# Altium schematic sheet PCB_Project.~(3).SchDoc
size 431 x 279 mm; Date: Not shown in title block; ApprovedBy: Not shown in title block; CheckedBy: Not shown in title block; Author: Not shown in title block; CompanyName: Not shown in title block; Engineer: Not shown in title block; Organization: Not shown in title block; Address1: Not shown in title block; Address2: Not shown in title block; Address3: Not shown in title block; Address4: Not shown in title block; DocumentNumber: 1; Revision: Use project parameter SCH_Rev; SheetNumber: 1; SheetTotal: 3; PageSetup: Record=PageOptions¦CenterHorizontal=True¦CenterVertical=True¦PrintScale=1.00¦XCorrection=1.00¦YCorrection=1.00¦PrintKind=0¦BorderSize=5000000¦LeftOffset=0¦BottomOffset=0¦Orientation=2¦PaperLength=1000¦PaperWidth=1000¦Scale=100¦PaperSource=15¦PrintQuality=600¦MediaType=1¦DitherType=10¦PaperKind=Letter¦PrintScaleMode=1
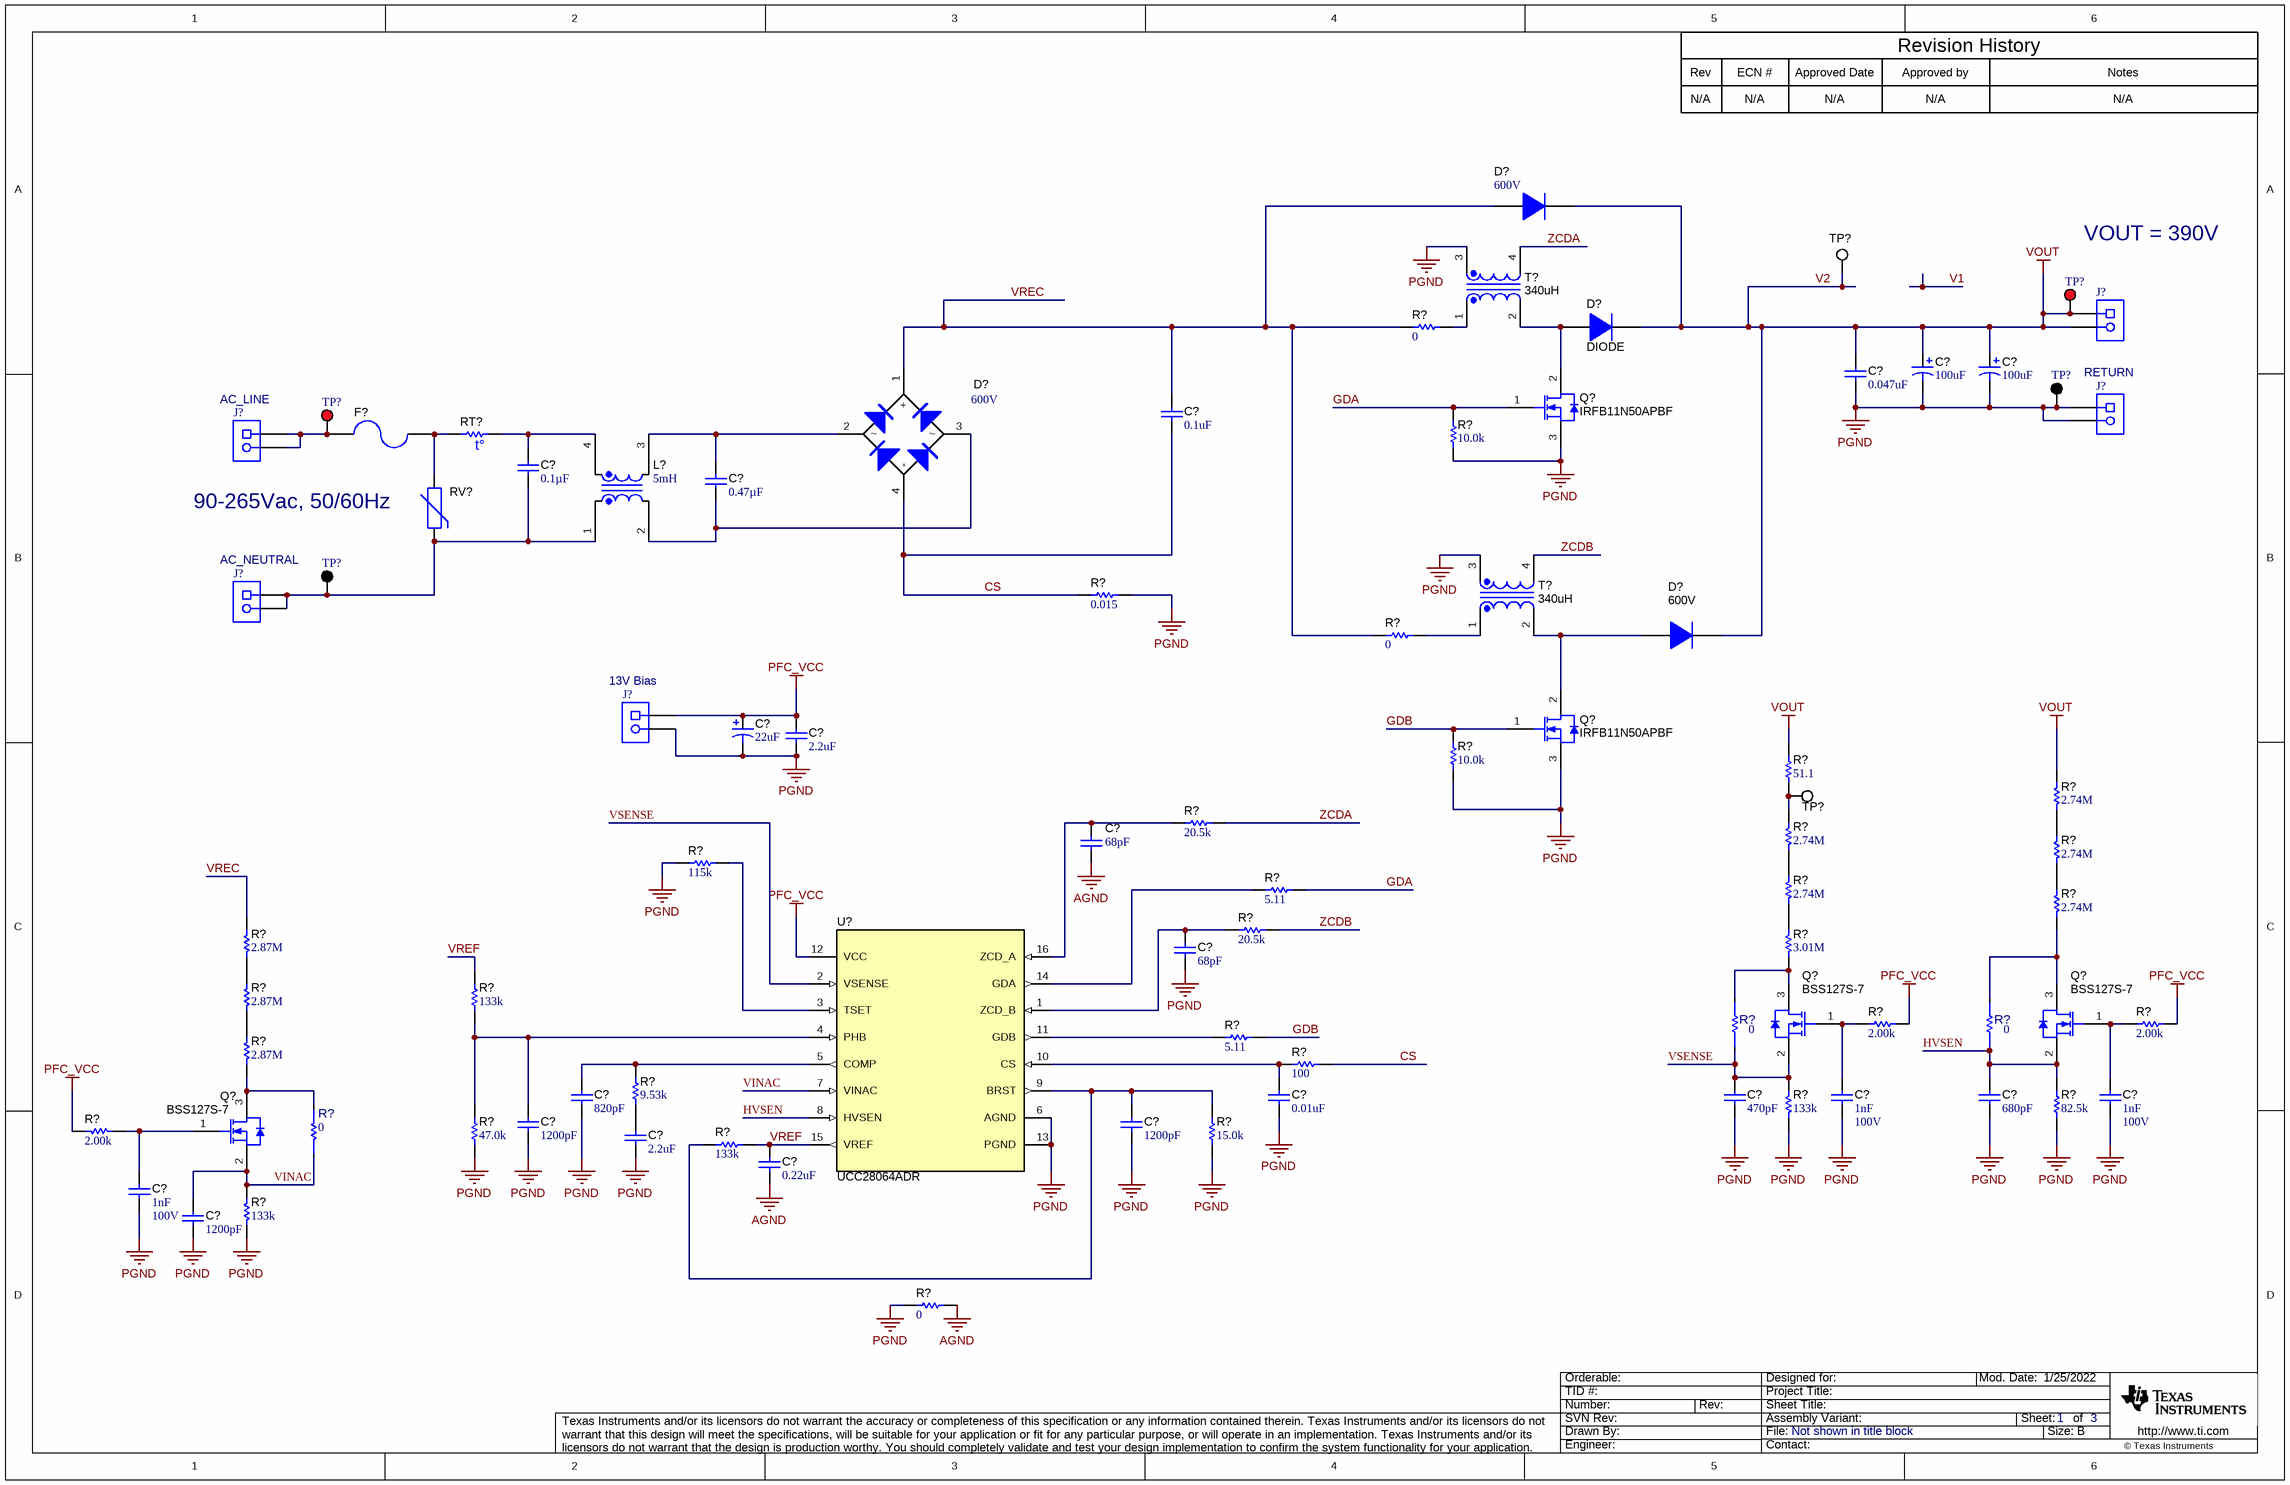
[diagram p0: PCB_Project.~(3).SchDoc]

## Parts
(Parts that share a designator on the sheet are numbered #1, #2 ... from top to bottom, then left to right.)
C?#1  ValueDisplayed: 0.047uF  [ECQE_1200x1450x650]  (hidden comment: Capacitor)
C?#2  ValueDisplayed: 100uF  [KXG_1800x4000_horizontalUp]  (hidden comment: Cap_Polarized)
C?#3  ValueDisplayed: 100uF  [KXG_1800x4000_horizontalDown]  (hidden comment: Cap_Polarized)
C?#4  ValueDisplayed: 0.1uF  [CAPRR1500W60L1750T550H1250]  (hidden comment: Capacitor)
C?#5  ValueDisplayed: 0.1µF  [Kemet_1800x500x1100]  (hidden comment: F863BC104K310Z)
C?#6  ValueDisplayed: 0.47µF  [PHE840M_2600x800x1600]  (hidden comment: PHE840MY6470MD14R06L2)
C?#7  ValueDisplayed: 2.2uF  [0805_HV]  (hidden comment: Capacitor)
C?#8  ValueDisplayed: 22uF  [M_500x1100]  (hidden comment: Cap_Polarized)
C?#9  ValueDisplayed: 68pF  [0805_HV]  (hidden comment: Capacitor)
C?#10  ValueDisplayed: 68pF  [0805_HV]  (hidden comment: Capacitor)
C?#11  ValueDisplayed: 820pF  [0805_HV]  (hidden comment: Capacitor)
C?#12  ValueDisplayed: 0.01uF  [0805_HV]  (hidden comment: Capacitor)
C?#13  ValueDisplayed: 470pF  [0805_HV]  (hidden comment: Capacitor)
C?#14  Cap_F: 1nF  VDC_V: 100V  [0603]  (hidden comment: C1608X7R2A102K080AA)
C?#15  ValueDisplayed: 680pF  [0805_HV]  (hidden comment: Capacitor)
C?#16  Cap_F: 1nF  VDC_V: 100V  [0603]  (hidden comment: C1608X7R2A102K080AA)
C?#17  ValueDisplayed: 1200pF  [0805_HV]  (hidden comment: Capacitor)
C?#18  ValueDisplayed: 1200pF  [0805_HV]  (hidden comment: Capacitor)
C?#19  ValueDisplayed: 2.2uF  [0805_HV]  (hidden comment: Capacitor)
C?#20  ValueDisplayed: 0.22uF  [1206]  (hidden comment: Capacitor)
C?#21  Cap_F: 1nF  VDC_V: 100V  [0603]  (hidden comment: C1608X7R2A102K080AA)
C?#22  ValueDisplayed: 1200pF  [0805_HV]  (hidden comment: Capacitor)
D?#1  Vr_V: 600V  [SMC]  (hidden comment: DIODE)
D?#2  DIODE  [SMC]
D?#3  Vr_V: 600V  [GBU_Horizontal_Down_Standoff2300]  (hidden comment: GBU6J)
D?#4  600V  [SMC]
F?  0216008.MXEP  [FUSE_0216]  (value not drawn)
J?#1  Receptacle_2x1  [On-Shore_ED120_2DS]  (value not drawn)
J?#2  Receptacle_2x1  [On-Shore_ED120_2DS]  (value not drawn)
J?#3  Receptacle_2x1  [On-Shore_ED120_2DS]  (value not drawn)
J?#4  Receptacle_2x1  [On-Shore_ED120_2DS]  (value not drawn)
J?#5  Receptacle_2x1  [On-Shore_ED120_2DS]  (value not drawn)
L?  ValueDisplayed: 5mH  [8100_8109-8114]  (hidden comment: INDUCTOR_COUPLED_12_43)
Q?#1  IRFB11N50APBF  [TO-220AB_Horizontal_100mil_Standoff2300]
Q?#2  IRFB11N50APBF  [TO-220AB_Horizontal_100mil_Standoff2300]
Q?#3  BSS127S-7  [SOT-23]
Q?#4  BSS127S-7  [SOT-23]
Q?#5  BSS127S-7  [SOT-23]
R?#1  ValueDisplayed: 0  [2512]  (hidden comment: Resistor)
R?#2  ValueDisplayed: 10.0k  [0805_HV]  (hidden comment: Resistor)
R?#3  ValueDisplayed: 0.015  [2010]  (hidden comment: Resistor)
R?#4  ValueDisplayed: 0  [2512]  (hidden comment: Resistor)
R?#5  ValueDisplayed: 10.0k  [0805_HV]  (hidden comment: Resistor)
R?#6  ValueDisplayed: 51.1  [0805_HV]  (hidden comment: Resistor)
R?#7  ValueDisplayed: 2.74M  [0805_HV]  (hidden comment: Resistor)
R?#8  ValueDisplayed: 20.5k  [0805_HV]  (hidden comment: Resistor)
R?#9  ValueDisplayed: 2.74M  [0805_HV]  (hidden comment: Resistor)
R?#10  ValueDisplayed: 2.74M  [0805_HV]  (hidden comment: Resistor)
R?#11  ValueDisplayed: 115k  [0805_HV]  (hidden comment: CRCW0805115KFKEA)
R?#12  ValueDisplayed: 5.11  [0805_HV]  (hidden comment: Resistor)
R?#13  ValueDisplayed: 2.74M  [0805_HV]  (hidden comment: Resistor)
R?#14  ValueDisplayed: 2.74M  [0805_HV]  (hidden comment: Resistor)
R?#15  ValueDisplayed: 20.5k  [0805_HV]  (hidden comment: Resistor)
R?#16  ValueDisplayed: 2.87M  [0805_HV]  (hidden comment: Resistor)
R?#17  ValueDisplayed: 3.01M  [0805_HV]  (hidden comment: Resistor)
R?#18  ValueDisplayed: 2.87M  [0805_HV]  (hidden comment: Resistor)
R?#19  ValueDisplayed: 133k  [0805_HV]  (hidden comment: CRCW0805133KFKEA)
R?#20  ValueDisplayed: 2.00k  [0603]  (hidden comment: RC0603FR-072KL)
R?#21  ValueDisplayed: 2.00k  [0603]  (hidden comment: RC0603FR-072KL)
R?#22  ValueDisplayed: 5.11  [0805_HV]  (hidden comment: Resistor)
R?#23  ValueDisplayed: 2.87M  [0805_HV]  (hidden comment: Resistor)
R?#24  value 0  [FP-RMCF1206ZT0R00_1206-MFG]  (hidden comment: RMCF1206ZT0R00)
R?#25  value 0  [FP-RMCF1206ZT0R00_1206-MFG]  (hidden comment: RMCF1206ZT0R00)
R?#26  ValueDisplayed: 100  [0805_HV]  (hidden comment: Resistor)
R?#27  ValueDisplayed: 9.53k  [0805_HV]  (hidden comment: Resistor)
R?#28  ValueDisplayed: 133k  [0805_HV]  (hidden comment: Resistor)
R?#29  ValueDisplayed: 82.5k  [0805_HV]  (hidden comment: Resistor)
R?#30  ValueDisplayed: 2.00k  [0603]  (hidden comment: RC0603FR-072KL)
R?#31  ValueDisplayed: 47.0k  [0805_HV]  (hidden comment: Resistor)
R?#32  ValueDisplayed: 15.0k  [0805_HV]  (hidden comment: CRCW080515K0FKEA)
R?#33  ValueDisplayed: 133k  [0805_HV]  (hidden comment: CRCW0805133KFKEA)
R?#34  value 0  [FP-RMCF1206ZT0R00_1206-MFG]  (hidden comment: RMCF1206ZT0R00)
R?#35  ValueDisplayed: 133k  [0805_HV]  (hidden comment: CRCW0805133KFKEA)
R?#36  ValueDisplayed: 0  [2512]  (hidden comment: Resistor)
RT?  CL-40  [Thermistor_CL-40]  (value not drawn)
RV?  Varistor_MetalOxide  [VAR_S10K275E2]  (value not drawn)
T?#1  340uH  [EATON_CTX16-17769-R]
T?#2  340uH  [EATON_CTX16-17769-R]
TP?#1  5002  [Keystone5002]  (value not drawn)
TP?#2  5010  [Keystone5010]  (value not drawn)
TP?#3  5011  [Keystone5011]  (value not drawn)
TP?#4  5010  [Keystone5010]  (value not drawn)
TP?#5  5011  [Keystone5011]  (value not drawn)
TP?#6  5002  [Keystone5002]  (value not drawn)
U?  UCC28064ADR  [D0016A_N]

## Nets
AGND: C?#9.2 C?#20.2 R?#36.1
PFC_VCC: C?#7.2 C?#8.1(+) J?#5.1 R?#20.2 R?#21.2 R?#30.2 U?.12(VCC)
PGND: C?#1.2 C?#2.2(-) C?#3.2(-) C?#7.1 C?#8.2(-) C?#10.1 C?#11.1 C?#12.2 C?#13.2 C?#14.2 C?#15.2 C?#16.2 C?#17.2 C?#18.2 C?#19.2 C?#21.2 C?#22.1 J?#2.1 J?#2.2 J?#5.2 Q?#1.3(S) Q?#2.3(S) R?#2.1 R?#3.2 R?#5.1 R?#11.1 R?#28.1 R?#29.1 R?#31.1 R?#32.1 R?#35.1 R?#36.2 T?#1.3 T?#2.3 TP?#3.1 U?.6(AGND) U?.13(PGND)
V2: C?#1.1 C?#2.1(+) C?#3.1(+) D?#1.1(K) D?#2.1(K) D?#4.1(K) J?#1.1 J?#1.2 R?#6.2 R?#7.2 TP?#1.1 TP?#2.1  [also labelled VOUT]
CS: C?#4.2 D?#3.4(-) R?#3.1 R?#26.2
GDA: Q?#1.1(G) R?#2.2 R?#12.2
GDB: Q?#2.1(G) R?#5.2 R?#22.2
HVSEN: C?#15.1 Q?#4.2(S) R?#25.1 R?#29.2 U?.8(HVSEN)
VINAC: C?#22.2 Q?#5.2(S) R?#34.1 R?#35.2 U?.7(VINAC)
VREC: C?#4.1 D?#1.2(A) D?#3.1(+) R?#1.1 R?#4.1 R?#16.1
VREF: C?#20.1 R?#19.2 R?#33.2 U?.15(VREF)
VSENSE: C?#13.1 Q?#3.2(S) R?#24.1 R?#28.2 U?.2(VSENSE)
ZCDA: R?#8.1 T?#1.4
ZCDB: R?#15.2 T?#2.4
NetC?#5_1: C?#5.1 L?.4 RT?.2
NetC?#5_2: C?#5.2 J?#4.1 J?#4.2 L?.1 RV?.2 TP?#5.1
NetC?#6_1: C?#6.1 D?#3.2 L?.3
NetC?#6_2: C?#6.2 D?#3.3 L?.2
NetC?#9_1: C?#9.1 R?#8.2 U?.16(ZCD_A)
NetC?#10_2: C?#10.2 R?#15.1 U?.1(ZCD_B)
NetC?#11_2: C?#11.2 R?#27.2 U?.5(COMP)
NetC?#12_1: C?#12.1 R?#26.1 U?.10(CS)
NetC?#14_1: C?#14.1 Q?#3.1(G) R?#20.1
NetC?#16_1: C?#16.1 Q?#4.1(G) R?#21.1
NetC?#17_1: C?#17.1 R?#19.1 R?#31.2 U?.4(PHB)
NetC?#18_1: C?#18.1 R?#32.2 R?#33.1 U?.9(BRST)
NetC?#19_1: C?#19.1 R?#27.1
NetC?#21_1: C?#21.1 Q?#5.1(G) R?#30.1
NetD?#2_2: D?#2.2(A) Q?#1.2(D) T?#1.2
NetD?#4_2: D?#4.2(A) Q?#2.2(D) T?#2.2
NetF?_1: F?.1 RT?.1 RV?.1
NetF?_2: F?.2 J?#3.1 J?#3.2 TP?#4.1
NetQ?#3_3: Q?#3.3(D) R?#17.2 R?#24.2
NetQ?#4_3: Q?#4.3(D) R?#14.1 R?#25.2
NetQ?#5_3: Q?#5.3(D) R?#23.1 R?#34.2
NetR?#1_2: R?#1.2 T?#1.1
NetR?#4_2: R?#4.2 T?#2.1
NetR?#6_1: R?#6.1 R?#9.1 TP?#6.1
NetR?#7_1: R?#7.1 R?#10.2
NetR?#9_2: R?#9.2 R?#13.1
NetR?#10_1: R?#10.1 R?#14.2
NetR?#11_2: R?#11.2 U?.3(TSET)
NetR?#12_1: R?#12.1 U?.14(GDA)
NetR?#13_2: R?#13.2 R?#17.1
NetR?#16_2: R?#16.2 R?#18.1
NetR?#18_2: R?#18.2 R?#23.2
NetR?#22_1: R?#22.1 U?.11(GDB)

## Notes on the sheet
- Rev
- N/A
- ECN #
- Approved Date
- Approved by
- Revision History
- Notes
- VOUT = 390V
- (near J?#3) AC_LINE
- RETURN
- 90-265Vac, 50/60Hz
- (near J?#4) AC_NEUTRAL
- (near J?#5) 13V Bias

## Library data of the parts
C?#1 = CMP-0012494-3: CAP, Film, 0.047 uF, 630 V, +/- 10%, TH; PartNumber: ECQ-E6473KF; Manufacturer: Panasonic; Polarized: N; Cap_F: 47nF; Value1: Unknown; VDC_V: 630V; TaMin_C: -40°C; TaMax_C: 105°C; Cap_Case: 12x14.5x6.5mm; SizeAreaWB_mm2: 119; SizeArea_mm2: 78; SizeX_mm: 12; SizeY_mm: 6.5; SizeZ_mm: 14.5; AEC Category: Q200
C?#2 C?#3 = CMP-0010042-2: CAP, AL, 100 uF, 450 V, +/- 20%, TH; PartNumber: EKXG451ELL101MM40S; Manufacturer: Chemi-Con; Polarized: Y; CompType: Capacitor; Value: 100uF; U/M: EA; Cap_F: 100µF; Value1: Unknown; VDC_V: 450V; IRMS_A: 8dA; TaMin_C: -25°C; TaMax_C: 105°C; Cap_Case: 18x40mm; SizeAreaWB_mm2: 400; SizeArea_mm2: 324; SizeX_mm: 18; SizeZ_mm: 41.5; AEC Category: Q200; AEC Qualified: N
C?#4 = CMP-0012496-3: CAP, Film, 0.1 uF, 275 V, +/- 20%, TH; PartNumber: ECQ-U2A104ML; Manufacturer: Panasonic; Polarized: N; Value: 0.1uF; Cap_F: 100nF; Value1: Unknown; VDC_V: 275V; TaMin_C: -40°C; TaMax_C: 100°C; Cap_Case: Radial 17.5x5.5x12.5; AEC Category: Q200
C?#5 = CMP-0079307-2: CAP, Film, 0.1 µF, X2 310 VAC, +/- 10%, AEC-Q200 Grade 1, TH; Manufacturer: Kemet; Cap_F: 100nF; SizeAreaWB_mm2: 140; SizeArea_mm2: 90; AEC Qualified: Y; AEC Category: Q200; Value: 0.1uF; TaMax_C: 110°C; SizeZ_mm: 11.1; AEC Grade: 1; Polarized: N; TaMin_C: -40°C; SizeY_mm: 5; CompType: Capacitor; SizeX_mm: 18; Cap_Case: 18x5x11mm; VAC_X: 310
C?#6 = CMP-0079470-1: CAP, Film, 0.47 µF, 760 V,+/- 20%, TH; Manufacturer: Kemet; Cap_F: 470nF; SizeAreaWB_mm2: 280; SizeArea_mm2: 208; AEC Qualified: N; AEC Category: Q200; Value: 0.47uF; TaMax_C: 105°C; SizeZ_mm: 16; TaMin_C: -55°C; VDC_V: 760V; SizeY_mm: 8; CompType: Capacitor; SizeX_mm: 26; Cap_Case: 26x8x16mm
C?#7 C?#19 = CMP-0007877-2: CAP, CERM, 2.2 uF, 50 V, +/- 10%, X7R, 0805; PartNumber: C2012X7R1H225K125AC; Manufacturer: TDK; Polarized: N; Value: 2.2uF; U/M: EA; Cap_F: 2.2µF; ESR_ohm: 3.66m; Value1: 0.00366 ohm; VDC_V: 50V; IRMS_A: 3.41207A; TaMin_C: -55°C; TaMax_C: 125°C; Cap_Case: 0805; SizeArea_mm2: 2.5; SizeAreaWB_mm2: 6.75; SizeX_mm: 2; SizeY_mm: 1.25; SizeZ_mm: 1.45; AEC Category: Q200
C?#8 = CMP-0010326-2: CAP, AL, 22 uF, 35 V, +/- 20%, TH; PartNumber: ECA-1VM220; Manufacturer: Panasonic; Polarized: Y; CompType: Capacitor; Value: 22uF; U/M: EA; Cap_F: 22µF; Value1: Unknown; VDC_V: 35V; IRMS_A: 95mA; TaMin_C: -40°C; TaMax_C: 85°C; Cap_Case: 5x11; SizeAreaWB_mm2: 49; SizeArea_mm2: 25; SizeX_mm: 5; SizeZ_mm: 12; AEC Category: Q200; AEC Qualified: N
C?#9 C?#10 = CMP-0007622-2: CAP, CERM, 68 pF, 50 V, +/- 5%, C0G/NP0, 0805; PartNumber: 08055A680JAT2A; Manufacturer: AVX; Polarized: N; Value: 68pF; U/M: EA; ESR_ohm: 4.5d; Value1: 0.45 ohm; VDC_V: 50V; TaMin_C: -55°C; TaMax_C: 125°C; Cap_Case: 0805; SizeArea_mm2: 2.5; SizeAreaWB_mm2: 6.75; SizeX_mm: 2; SizeY_mm: 1.25; SizeZ_mm: 1.45; AEC Category: Q200
C?#11 = CMP-0008153-2: CAP, CERM, 820 pF, 25 V, +/- 10%, X7R, 0805; PartNumber: GRM216R71E821KA01D; Manufacturer: MuRata; Polarized: N; Value: 820pF; U/M: EA; Value1: Unknown; VDC_V: 25V; TaMin_C: -55°C; TaMax_C: 125°C; Cap_Case: 0805; SizeArea_mm2: 2.5; SizeAreaWB_mm2: 6.75; SizeX_mm: 2; SizeY_mm: 1.25; SizeZ_mm: 1.45; AEC Category: Q200
C?#12 = CMP-0007629-2: CAP, CERM, 0.01 uF, 50 V, +/- 5%, X7R, 0805; PartNumber: 08055C103JAT2A; Manufacturer: AVX; Polarized: N; Value: 0.01uF; U/M: EA; Cap_F: 10nF; ESR_ohm: 0.078; Value1: 0.078 ohm; VDC_V: 50V; TaMin_C: -55°C; TaMax_C: 125°C; Cap_Case: 0805; SizeArea_mm2: 2.5; SizeAreaWB_mm2: 6.75; SizeX_mm: 2; SizeY_mm: 1.25; SizeZ_mm: 1.45; AEC Category: Q200
C?#13 = CMP-0008150-2: CAP, CERM, 470 pF, 25 V, +/- 10%, X7R, 0805; PartNumber: GRM216R71E471KA01D; Manufacturer: MuRata; Polarized: N; Value: 470pF; U/M: EA; Value1: Unknown; VDC_V: 25V; TaMin_C: -55°C; TaMax_C: 125°C; Cap_Case: 0805; SizeArea_mm2: 2.5; SizeAreaWB_mm2: 6.75; SizeX_mm: 2; SizeY_mm: 1.25; SizeZ_mm: 1.45; AEC Category: Q200
C?#14 C?#16 C?#21 = CMP-0007053-4: CAP, CERM, 1000 pF, 100 V, +/- 10%, X7R, 0603; Manufacturer: TDK; TaMin_C: -55°C; Polarized: N; SizeAreaWB_mm2: 4.68; Value1: Unknown; U/M: EA; Value: 1000pF; TaMax_C: 125°C; SizeZ_mm: 1; SizeX_mm: 1.6; SizeY_mm: 0.8; SizeArea_mm2: 1.28; AEC Category: Q200
C?#15 = CMP-0007693-2: CAP, CERM, 680 pF, 25 V, +/- 10%, X7R, 0805; PartNumber: 885012207059; Manufacturer: Wurth Elektronik; Polarized: N; Value: 680pF; U/M: EA; Value1: Unknown; VDC_V: 25V; TaMin_C: -55°C; TaMax_C: 125°C; Cap_Case: 0805; SizeArea_mm2: 2.5; SizeAreaWB_mm2: 6.75; SizeX_mm: 2; SizeY_mm: 1.25; SizeZ_mm: 1.45; AEC Category: Q200
C?#17 C?#18 C?#22 = CMP-0008142-2: CAP, CERM, 1200 pF, 25 V, +/- 10%, X7R, 0805; PartNumber: GRM216R71E122KA01D; Manufacturer: MuRata; Polarized: N; Value: 1200pF; U/M: EA; Cap_F: 1.2nF; Value1: Unknown; VDC_V: 25V; TaMin_C: -55°C; TaMax_C: 125°C; Cap_Case: 0805; SizeArea_mm2: 2.5; SizeAreaWB_mm2: 6.75; SizeX_mm: 2; SizeY_mm: 1.25; SizeZ_mm: 1.45; AEC Category: Q200
C?#20 = CMP-0008995-2: CAP, CERM, 0.22 uF, 50 V, +/- 10%, X7R, 1206; PartNumber: GRM31MR71H224KA01L; Manufacturer: MuRata; Polarized: N; Value: 0.22uF; U/M: EA; Cap_F: 220nF; Value1: Unknown; VDC_V: 50V; TaMin_C: -55°C; TaMax_C: 125°C; SizeArea_mm2: 5.12; SizeAreaWB_mm2: 10.92; SizeX_mm: 3.2; SizeY_mm: 1.6; SizeZ_mm: 1.35; AEC Category: Q200
D?#1 D?#2 = CMP-0076905-1: Diode, Ultrafast, 600 V, 3 A, SMC; PartNumber: MURS360T3G; Manufacturer: ON Semiconductor; U/M: EA; Vf_V: 1.25V; Value: 600V; Value1: 3A; TJmax_C: 175°C; RJC_CperW: 11.0; SizeAreaWB_mm2: 83.2686; SizeArea_mm2: 50.5686; SizeX_mm: 8.13; SizeY_mm: 6.22; SizeZ_mm: 2.6; AEC Category: Q101; Green_Lifecycle: Active; Green_REACh: Passed
D?#3 = CMP-0029269-2: Diode, Switching-Bridge, 600 V, 6 A, TH; Manufacturer: Fairchild Semiconductor; U/M: EA; Vf_V: 1V; Value: 600V; Value1: 6A; TJmax_C: 150°C; RJC_CperW: 3.1; SizeAreaWB_mm2: 130.5915; SizeArea_mm2: 75.6315; SizeX_mm: 22.05; SizeY_mm: 3.43; SizeZ_mm: 21.55; AEC Category: Q101; AEC Qualified: N; Green_Lifecycle: Active; Green_REACh: Passed
D?#4 = CMP-0076905-1: Diode, Ultrafast, 600 V, 3 A, SMC; PartNumber: MURS360T3G; Manufacturer: ON Semiconductor; U/M: EA; Vf_V: 1.25V; Value1: 3A; TJmax_C: 175°C; RJC_CperW: 11.0; SizeAreaWB_mm2: 83.2686; SizeArea_mm2: 50.5686; SizeX_mm: 8.13; SizeY_mm: 6.22; SizeZ_mm: 2.6; AEC Category: Q101; Green_Lifecycle: Active; Green_REACh: Passed
F? = CMP-0079917-1: Fuse, 8 A, 250 VAC, TH; Manufacturer: Littelfuse; VAC_V: 250V; Rtyp_Ohm: 0.0123; MeltingTyp: 64.315; Irating_A: 8A; Interrupt_AC: 1.5kA
J?#1-J?#5 = CMP-0074910-1: Terminal Block, 5.08 mm, 2x1, Brass, TH; PartNumber: ED120/2DS; Manufacturer: On-Shore Technology; Pitch_mm: 5.08; Gender: Female; Shrouded: N; Row_Count: 1; Current_A: 15A; Voltage_V: 300V; Cert_CULUS: Y; Green_Lifecycle: Not Set; Green_REACh: Incomplete; CNHeader: False; CT: True
L? = CMP-0076835-1: Coupled inductor, 5 mH, 8.9 A, 0.022 ohm, TH; PartNumber: 8113-RC; Manufacturer: Bourns; Value: 5mH; DCR_ohm: 0.022; Green_Lifecycle: Not Set; Green_REACh: Incomplete; AEC Category: Q200
Q?#1 Q?#2 = CMP-0001125-3: MOSFET, N-CH, 500 V, 11 A, AEC-Q101, TO-220AB; Alternate Manufacturer: None; Manufacturer: Vishay-Siliconix; SizeZ_mm: 19.4; ChType: N; Value2: 52 nC; VdsMax_V: 500V; SizeX_mm: 10.2; SizeY_mm: 4.5; Vgs_V: 30V; AEC Qualified: Y; Value: 500V; SizeArea_mm2: 45.9; AEC Category: Q101; IdsMax_A: 11A; SizeAreaWB_mm2: 79.3; U/M: EA; QgTyp_nC: 52
Q?#3-Q?#5 = CMP-0001149-3: MOSFET, N-CH, 600 V, 0.05 A, SOT-23; Alternate Manufacturer: None; Manufacturer: Diodes Inc.; SizeZ_mm: 1.1; ChType: N; Value2: 1.08 nC; VdsMax_V: 600V; SizeX_mm: 2.5; SizeY_mm: 3; Vgs_V: 20V; QgTyp_nC: 1.08; Value: 600V; SizeArea_mm2: 7.5; AEC Category: Q101; IdsMax_A: 50mA; SizeAreaWB_mm2: 14; U/M: EA
R?#1 R?#4 R?#36 = CMP-0015864-3: RES, 0, 5%, 1 W, AEC-Q200 Grade 0, 2512; PartNumber: CRCW25120000Z0EG; Manufacturer: Vishay-Dale; Value: 0; Value_Code: 0000; Power_W: 1W; TempCo: ppm/C; SizeArea_mm2: 20.16; SizeX_mm: 6.3; SizeY_mm: 3.2; SizeZ_mm: 0.71; EIA_Code: E24; AEC Category: Q200; AEC Qualified: Y
R?#2 R?#5 = CMP-0020842-3: RES, 10.0 k, 1%, 0.125 W, AEC-Q200 Grade 0, 0805; PartNumber: CRCW080510K0FKEA; Manufacturer: Vishay-Dale; Value: 10.0k; Res_ohm: 10k; Value_Code: 10k0; Power_W: 125mW; Value2: 0.125W; VDC_V: 150V; TempCo: 100 ppm/C; SizeArea_mm2: 2.5; SizeX_mm: 2; SizeY_mm: 1.25; SizeZ_mm: 1.45; EIA_Code: E96; AEC Category: Q200; AEC Qualified: Y; AEC Grade: 0
R?#3 = CMP-0016558-2: RES, 0.015, 1%, 0.5 W, 2010; PartNumber: WSL2010R0150FEA; Manufacturer: Vishay-Dale; Value: 0.015; Value_Code: R015; Power_W: 500mW; Value2: 0.5W; TempCo: 75 ppm/C; SizeArea_mm2: 12.5; SizeX_mm: 5; SizeY_mm: 2.5; SizeZ_mm: 1.66; EIA_Code: E96; U/M: EA; AEC Category: Q200
R?#6 = CMP-0020156-2: RES, 51.1, 0.1%, 0.125 W, 0805; PartNumber: RT0805BRD0751R1L; Manufacturer: Yageo America; Value: 51.1; Value_Code: 51R1; Power_W: 125mW; Value2: 0.125W; VDC_V: 150V; TempCo: 25 ppm/C; SizeArea_mm2: 2.5; SizeX_mm: 2; SizeY_mm: 1.25; SizeZ_mm: 1.45; EIA_Code: E192; U/M: EA; AEC Category: Q200
R?#7 R?#9 R?#10 R?#13 R?#14 = CMP-0021137-3: RES, 2.74 M, 1%, 0.125 W, AEC-Q200 Grade 0, 0805; PartNumber: CRCW08052M74FKEA; Manufacturer: Vishay-Dale; Value: 2.74Meg; Value_Code: 2M74; Power_W: 125mW; Value2: 0.125W; VDC_V: 150V; TempCo: 100 ppm/C; SizeArea_mm2: 2.5; SizeX_mm: 2; SizeY_mm: 1.25; SizeZ_mm: 1.45; EIA_Code: E96; AEC Category: Q200; AEC Qualified: Y; AEC Grade: 0
R?#8 R?#15 = CMP-0021043-3: RES, 20.5 k, 1%, 0.125 W, AEC-Q200 Grade 0, 0805; PartNumber: CRCW080520K5FKEA; Manufacturer: Vishay-Dale; Value: 20.5k; Value_Code: 20k5; Power_W: 125mW; Value2: 0.125W; VDC_V: 150V; TempCo: 100 ppm/C; SizeArea_mm2: 2.5; SizeX_mm: 2; SizeY_mm: 1.25; SizeZ_mm: 1.45; EIA_Code: E96; AEC Category: Q200; AEC Qualified: Y; AEC Grade: 0
R?#11 = CMP-0020855-3: RES, 115 k, 1%, 0.125 W, AEC-Q200 Grade 0, 0805; Manufacturer: Vishay-Dale; Power_W: 125mW; TempCo: 100 ppm/C; Value: 115k; EIA_Code: E96; SizeX_mm: 2; SizeY_mm: 1.25; SizeZ_mm: 1.45; Value2: 0.125W; SizeArea_mm2: 2.5; AEC Qualified: Y; VDC_V: 150V; AEC Category: Q200; AEC Grade: 0
R?#12 R?#22 = CMP-0021358-3: RES, 5.11, 1%, 0.125 W, AEC-Q200 Grade 0, 0805; PartNumber: CRCW08055R11FKEA; Manufacturer: Vishay-Dale; Value: 5.11; Value_Code: 5R11; Power_W: 125mW; Value2: 0.125W; VDC_V: 150V; TempCo: 100 ppm/C; SizeArea_mm2: 2.5; SizeX_mm: 2; SizeY_mm: 1.25; SizeZ_mm: 1.45; EIA_Code: E96; AEC Category: Q200; AEC Qualified: Y; AEC Grade: 0
R?#16 R?#18 R?#23 = CMP-0021139-3: RES, 2.87 M, 1%, 0.125 W, AEC-Q200 Grade 0, 0805; PartNumber: CRCW08052M87FKEA; Manufacturer: Vishay-Dale; Value: 2.87Meg; Value_Code: 2M87; Power_W: 125mW; Value2: 0.125W; VDC_V: 150V; TempCo: 100 ppm/C; SizeArea_mm2: 2.5; SizeX_mm: 2; SizeY_mm: 1.25; SizeZ_mm: 1.45; EIA_Code: E96; AEC Category: Q200; AEC Qualified: Y; AEC Grade: 0
R?#17 = CMP-0021219-4: RES, 3.01 M, 1%, 0.125 W, AEC-Q200 Grade 0, 0805; PartNumber: CRCW08053M01FKEA; Manufacturer: Vishay-Dale; Value: 3.01Meg; Value_Code: 3M01; Power_W: 125mW; Value2: 0.125W; VDC_V: 150V; TempCo: 100 ppm/C; SizeArea_mm2: 2.5; SizeX_mm: 2; SizeY_mm: 1.25; SizeZ_mm: 1.45; EIA_Code: E96; AEC Category: Q200; AEC Qualified: Y; AEC Grade: 0
R?#19 R?#33 R?#35 = CMP-0020881-3: RES, 133 k, 1%, 0.125 W, AEC-Q200 Grade 0, 0805; Manufacturer: Vishay-Dale; Power_W: 125mW; TempCo: 100 ppm/C; Value: 133k; EIA_Code: E96; SizeX_mm: 2; SizeY_mm: 1.25; SizeZ_mm: 1.45; Value2: 0.125W; SizeArea_mm2: 2.5; AEC Qualified: Y; VDC_V: 150V; AEC Category: Q200; AEC Grade: 0
R?#20 R?#21 R?#30 = CMP-0023000-5: RES, 2.00 k, 1%, 0.1 W, 0603; Manufacturer: Yageo; Power_W: 100mW; TempCo: 100 ppm/C; Value_Code: 2k00; Value: 2.00k; EIA_Code: E96; Res_ohm: 2k; SizeX_mm: 1.6; SizeY_mm: 0.8; SizeZ_mm: 1; Value2: 0.1W; SizeArea_mm2: 1.28; AEC Qualified: N; VDC_V: 75V; AEC Category: Q200; SizeAreaWB_mm2: 4.68
R?#24 R?#25 R?#34 = CMP-0093609-1: 0Ω ±0 0.25W 1206 Thick Film Chip Resistor AEC-Q200 compliant; Manufacturer: Stackpole Electronics; AEC Qualified: Yes; VDC_V: 200V; AEC Grade: Grade 0; Power_W: 250mW; SizeZ_mm: 0.7mm
R?#26 = CMP-0020835-3: RES, 100, 1%, 0.125 W, AEC-Q200 Grade 0, 0805; PartNumber: CRCW0805100RFKEA; Manufacturer: Vishay-Dale; Value: 100; Value_Code: 100R; Power_W: 125mW; Value2: 0.125W; VDC_V: 150V; TempCo: 100 ppm/C; SizeArea_mm2: 2.5; SizeX_mm: 2; SizeY_mm: 1.25; SizeZ_mm: 1.45; EIA_Code: E96; AEC Category: Q200; AEC Qualified: Y; AEC Grade: 0
R?#27 = CMP-0021817-2: RES, 9.53 k, 1%, 0.125 W, 0805; PartNumber: ERJ-6ENF9531V; Manufacturer: Panasonic; Value: 9.53k; Value_Code: 9k53; Power_W: 125mW; Value2: 0.125W; TempCo: 100 ppm/C; SizeArea_mm2: 2.5; SizeX_mm: 2; SizeY_mm: 1.25; SizeZ_mm: 1.45; EIA_Code: E96; U/M: EA; AEC Category: Q200
R?#28 = CMP-0020881-3: RES, 133 k, 1%, 0.125 W, AEC-Q200 Grade 0, 0805; PartNumber: CRCW0805133KFKEA; Manufacturer: Vishay-Dale; Value: 133k; Power_W: 125mW; Value2: 0.125W; VDC_V: 150V; TempCo: 100 ppm/C; SizeArea_mm2: 2.5; SizeX_mm: 2; SizeY_mm: 1.25; SizeZ_mm: 1.45; EIA_Code: E96; AEC Category: Q200; AEC Qualified: Y; AEC Grade: 0
R?#29 = CMP-0021455-3: RES, 82.5 k, 1%, 0.125 W, AEC-Q200 Grade 0, 0805; PartNumber: CRCW080582K5FKEA; Manufacturer: Vishay-Dale; Value: 82.5k; Value_Code: 82k5; Power_W: 125mW; Value2: 0.125W; VDC_V: 150V; TempCo: 100 ppm/C; SizeArea_mm2: 2.5; SizeX_mm: 2; SizeY_mm: 1.25; SizeZ_mm: 1.45; EIA_Code: E96; AEC Category: Q200; AEC Qualified: Y; AEC Grade: 0
R?#31 = CMP-0021726-2: RES, 47.0 k, 1%, 0.125 W, 0805; PartNumber: ERJ-6ENF4702V; Manufacturer: Panasonic; Value: 47.0k; Res_ohm: 47k; Value_Code: 47k0; Power_W: 125mW; Value2: 0.125W; VDC_V: 150V; TempCo: 100 ppm/C; SizeArea_mm2: 2.5; SizeX_mm: 2; SizeY_mm: 1.25; SizeZ_mm: 1.45; U/M: EA; AEC Category: Q200
R?#32 = CMP-0020909-3: RES, 15.0 k, 1%, 0.125 W, AEC-Q200 Grade 0, 0805; Manufacturer: Vishay-Dale; Power_W: 125mW; TempCo: 100 ppm/C; Value_Code: 15k0; Value: 15.0k; EIA_Code: E96; Res_ohm: 15k; SizeX_mm: 2; SizeY_mm: 1.25; SizeZ_mm: 1.45; Value2: 0.125W; SizeArea_mm2: 2.5; AEC Qualified: Y; VDC_V: 150V; AEC Category: Q200; AEC Grade: 0
RT? = CMP-0002561-2: Thermistor NTC, 5 ohm, 25%, Disc, 220x770 mil; Manufacturer: GE Sensing; Value: 5; Power_W: 180W; TaMin_C: -50°C; TaMax_C: 175°C; SizeAreaWB_mm2: 163.6404; SizeArea_mm2: 109.3404; SizeX_mm: 19.56; SizeY_mm: 5.59; U/M: EA
RV? = CMP-0002100-2: Varistor 275V RMS 10MM Radial, TH; PartNumber: S10K275E2; Manufacturer: TDK; SizeAreaWB_mm2: 103.6; SizeArea_mm2: 64.8; SizeX_mm: 12; SizeY_mm: 5.4; SizeZ_mm: 14.5
T?#1 T?#2 = CMP-0030075-1: Transformer, 340 uH, TH; PartNumber: CTX16-17769-R; Manufacturer: Eaton; DCR_ohm: 2.4d; Lp: 340; Ind_H: 340µH; Ns1toNp: 8; Rsec1_ohm: 0.035; SizeAreaWB_mm2: 1764; SizeArea_mm2: 1600; SizeX_mm: 40; SizeZ_mm: 19.8
TP?#1 TP?#6 = CMP-0055139-1: Test Point, Miniature, White, TH; Manufacturer: Keystone; CNHeader: FALSE; Green_Lifecycle: Active; Green_REACh: Passed; ContactFinish: Silver; CT: TRUE
TP?#2 TP?#4 = CMP-0055147-2: Test Point, Multipurpose, Red, TH; Manufacturer: Keystone Electronics; CT: TRUE; ContactFinish: Silver; Green_Lifecycle: Active; CNHeader: FALSE; Green_REACh: Passed
TP?#3 TP?#5 = CMP-0055148-2: Test Point, Multipurpose, Black, TH; Manufacturer: Keystone Electronics; CNHeader: FALSE; ContactFinish: Silver; Green_REACh: Passed; Green_Lifecycle: Active; CT: TRUE
U? = CMP-0065070-4: Natural Interleaving Transition Mode PFC Controller with Improved Light Load Efficiency, D0016A (SOIC-16); Manufacturer: Texas Instruments; SizeX_mm: 6.0; SizeY_mm: 9.9; CompType: IC; SizeZ_mm: 1.75; SizeArea_mm2: 59.4; SizeAreaWB_mm2: 95.2; U/M: EA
